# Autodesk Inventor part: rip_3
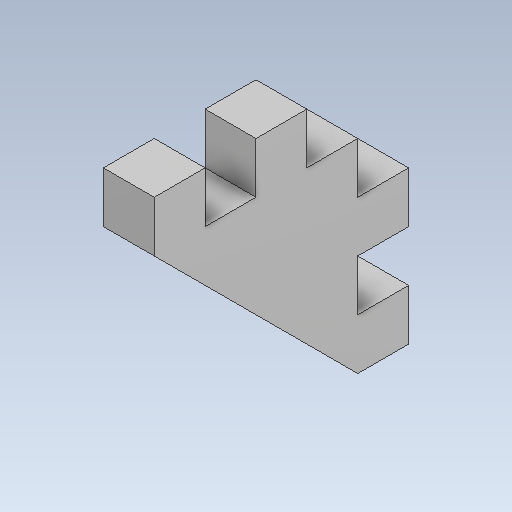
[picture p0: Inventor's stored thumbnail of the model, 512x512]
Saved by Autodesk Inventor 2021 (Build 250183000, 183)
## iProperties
Created: 2026-10
Part Number: rip_3
Material: Generic
Document SubType Name: Modeling
Designer: hp
Density: 1 g/cm^3
Appearance: Default
Author: hp
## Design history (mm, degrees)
feature "Body1"
body "Solid1"
